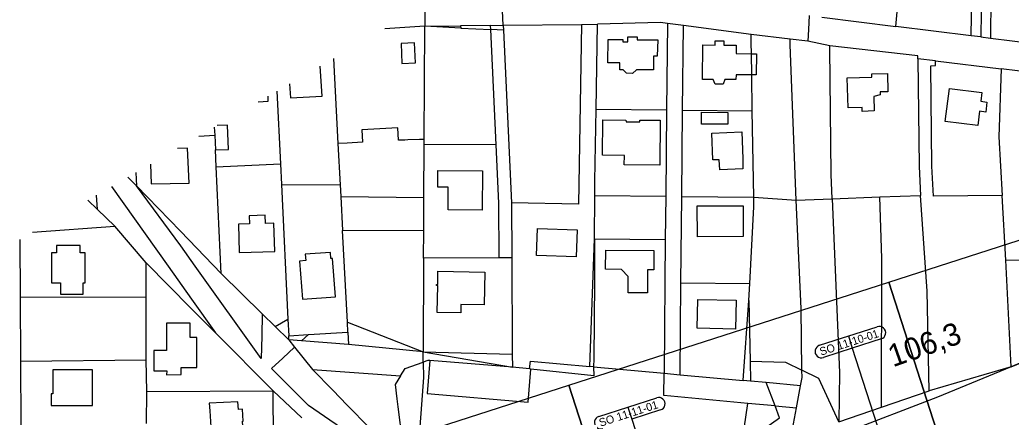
# Model space of a CAD drawing. Extents: x -758836 to -757729, y -1175316 to -1174366.
# Drawn here: x -758589.2 to -758279.4, y -1174765.3 to -1174641.1 of the extents above; entities that cross this region are included whole.
import ezdxf

# ---------------------------------------------------------------- set-up
doc = ezdxf.new("R2010")
doc.units = 0
for name, color, linetype in [('_NOR-návrh tenká', 7, 'Continuous'), ('_NOR-pomocná', 7, 'Continuous'), ('_NOR-popis', 7, 'Continuous'), ('G_Obvod stavby', 7, 'Continuous'), ('Hranice parcel', 7, 'Continuous'), ('Vrstva 7', 7, 'Continuous')]:
    doc.layers.add(name, color=color, linetype=linetype)

msp = doc.modelspace()

# ---------------------------------------------------------------- linework, layer by layer
at = {"layer": '_NOR-návrh tenká'}
msp.add_arc((-758205.34, -1175057.86), 295.6, 97.0978, 129.2849, dxfattribs=at)
at = {"layer": '_NOR-pomocná'}
for p, q in [((-758330.28, -1174739.89), (-758329.06, -1174743.7)), ((-758399.22, -1174762.1), (-758398, -1174765.9))]:
    msp.add_line(p, q, dxfattribs=at)
for points in [[(-758317.65, -1174723.03), (-758217.71, -1174690.84), (-758172.18, -1174832.19), (-758272.12, -1174864.38)], [(-758417.59, -1174755.22), (-758317.65, -1174723.03), (-758272.12, -1174864.38), (-758372.07, -1174896.57)], [(-758517.54, -1174787.42), (-758417.59, -1174755.22), (-758372.07, -1174896.57), (-758472.01, -1174928.76)]]:
    msp.add_lwpolyline(points, close=True, dxfattribs=at)
at = {"layer": '_NOR-popis'}
for points in [[(-758339.33, -1174742.8), (-758321.24, -1174736.98)], [(-758320.02, -1174740.79), (-758329.06, -1174743.7), (-758315.87, -1174784.63)], [(-758329.06, -1174743.7), (-758338.1, -1174746.61)], [(-758408.27, -1174765.01), (-758390.18, -1174759.18)], [(-758388.95, -1174762.99), (-758398, -1174765.9), (-758378.82, -1174825.45)]]:
    msp.add_lwpolyline(points, dxfattribs=at)
for centre, start, end in [((-758320.63, -1174738.88), 287.8533, 107.854), ((-758338.71, -1174744.71), 107.854, 287.8547), ((-758389.57, -1174761.09), 287.8533, 107.854), ((-758407.65, -1174766.91), 107.854, 287.8547)]:
    msp.add_arc(centre, 2, start, end, dxfattribs=at)
at = {"layer": 'G_Obvod stavby'}
msp.add_lwpolyline([(-758392.72, -1174840.76), (-758391.23, -1174838.56), (-758368.37, -1174821.64), (-758340.31, -1174807.33), (-758320.27, -1174796.89), (-758301, -1174790.21), (-758267.96, -1174782.93), (-758224.96, -1174775.27), (-758184.87, -1174772.83), (-758142.71, -1174770.26), (-758089.84, -1174768.68), (-758106.02, -1174731.44), (-758149.09, -1174725.67), (-758199.62, -1174726.6), (-758225.76, -1174732.36), (-758252.17, -1174738.18), (-758254.97, -1174739.34), (-758266.58, -1174744.16), (-758279.45, -1174749.49), (-758302.42, -1174759.02), (-758331.68, -1174770.24), (-758367.17, -1174799.81), (-758405.64, -1174832.2)], dxfattribs=at)
at = {"layer": 'Hranice parcel'}
for p, q in [((-758285.46, -1174607.47), (-758285.9, -1174646.82)), ((-758338.6, -1174640.24), (-758315.47, -1174643.12)), ((-758462.68, -1174643.09), (-758475.19, -1174643.89)), ((-758462.85, -1174678.46), (-758462.68, -1174643.09)), ((-758462.68, -1174643.09), (-758451.46, -1174642.95)), ((-758451.39, -1174643.67), (-758462.68, -1174643.09)), ((-758442.12, -1174642.84), (-758451.46, -1174642.95)), ((-758451.46, -1174642.95), (-758451.39, -1174643.67)), ((-758442.12, -1174642.84), (-758438.13, -1174642.79)), ((-758442.06, -1174644.14), (-758442.12, -1174642.84)), ((-758438.13, -1174642.79), (-758413.7, -1174642.5)), ((-758438.13, -1174642.79), (-758438.05, -1174644.35)), ((-758413.7, -1174642.5), (-758414.62, -1174698.66)), ((-758413.7, -1174642.5), (-758408.7, -1174642.44)), ((-758409.14, -1174669.01), (-758408.7, -1174642.44)), ((-758386.84, -1174642.22), (-758387.1, -1174669.22)), ((-758381.85, -1174642.89), (-758386.84, -1174642.22)), ((-758382.1, -1174669.27), (-758381.85, -1174642.89)), ((-758360.69, -1174645.71), (-758381.85, -1174642.89)), ((-758291.89, -1174646.05), (-758315.47, -1174643.12)), ((-758451.39, -1174643.67), (-758442.06, -1174644.14)), ((-758438.05, -1174644.35), (-758442.06, -1174644.14)), ((-758440.39, -1174680.2), (-758442.06, -1174644.14)), ((-758438.05, -1174644.35), (-758435.54, -1174698.32)), ((-758348.5, -1174647.1), (-758360.69, -1174645.71)), ((-758288.89, -1174646.43), (-758291.89, -1174646.05)), ((-758288.89, -1174646.43), (-758285.9, -1174646.82)), ((-758342.92, -1174647.74), (-758348.5, -1174647.1)), ((-758336.11, -1174649.25), (-758342.92, -1174647.74)), ((-758285.9, -1174646.82), (-758261.03, -1174649.91)), ((-758360.49, -1174658.29), (-758360.6, -1174651.67)), ((-758491.19, -1174653.13), (-758489.78, -1174679.76)), ((-758303.07, -1174653.93), (-758308.57, -1174653.26)), ((-758303.07, -1174653.93), (-758282.56, -1174656.41)), ((-758360.31, -1174669.48), (-758360.49, -1174658.29)), ((-758266.75, -1174658.35), (-758282.56, -1174656.41)), ((-758508.89, -1174663.35), (-758507.79, -1174686.07)), ((-758409.14, -1174669.01), (-758387.1, -1174669.22)), ((-758387.1, -1174669.22), (-758387.36, -1174696.22)), ((-758382.36, -1174696.27), (-758382.1, -1174669.27)), ((-758382.1, -1174669.27), (-758360.31, -1174669.48)), ((-758359.87, -1174696.48), (-758360.31, -1174669.48)), ((-758533.22, -1174677.4), (-758528.3, -1174677.14)), ((-758528.42, -1174674.62), (-758528.3, -1174677.14)), ((-758528.3, -1174677.14), (-758528.09, -1174681.75)), ((-758489.78, -1174679.76), (-758489.1, -1174692.62)), ((-758462.93, -1174696.59), (-758462.86, -1174680.09)), ((-758462.86, -1174680.09), (-758462.85, -1174678.46)), ((-758440.39, -1174680.2), (-758462.86, -1174680.09)), ((-758527.85, -1174687.07), (-758528.09, -1174681.75)), ((-758527.85, -1174687.07), (-758507.79, -1174686.07)), ((-758507.79, -1174686.07), (-758507.47, -1174692.57)), ((-758552.91, -1174688.76), (-758552.78, -1174692.96)), ((-758526.24, -1174720.38), (-758527.85, -1174687.07)), ((-758555.41, -1174690.21), (-758552.78, -1174692.96)), ((-758507.47, -1174692.57), (-758489.1, -1174692.62)), ((-758507.47, -1174692.57), (-758505.43, -1174734.65)), ((-758489.1, -1174692.62), (-758488.9, -1174696.33)), ((-758409.59, -1174709.5), (-758409.52, -1174696)), ((-758409.52, -1174696), (-758387.36, -1174696.22)), ((-758320.43, -1174696.43), (-758307.71, -1174695.96)), ((-758281.06, -1174716.22), (-758282.22, -1174695.95)), ((-758488.9, -1174696.33), (-758488.35, -1174706.88)), ((-758488.9, -1174696.33), (-758462.93, -1174696.59)), ((-758462.98, -1174706.79), (-758462.93, -1174696.59)), ((-758414.62, -1174698.66), (-758435.54, -1174698.32)), ((-758435.54, -1174698.32), (-758435.46, -1174715.46)), ((-758387.36, -1174696.22), (-758387.49, -1174709.72)), ((-758382.62, -1174723.27), (-758382.36, -1174696.27)), ((-758382.36, -1174696.27), (-758359.87, -1174696.48)), ((-758359.87, -1174696.48), (-758346.61, -1174697.42)), ((-758346.61, -1174697.42), (-758335.32, -1174696.99)), ((-758335.32, -1174696.99), (-758320.43, -1174696.43)), ((-758559.48, -1174705.52), (-758564.95, -1174700.34)), ((-758585.29, -1174707.46), (-758559.48, -1174705.52)), ((-758549.77, -1174716.98), (-758559.48, -1174705.52)), ((-758488.35, -1174706.88), (-758462.98, -1174706.79)), ((-758486.83, -1174735.54), (-758488.35, -1174706.88)), ((-758463.02, -1174715.59), (-758462.98, -1174706.79)), ((-758589.2, -1174709.72), (-758589.11, -1174727.75)), ((-758411.05, -1174749.38), (-758409.59, -1174709.5)), ((-758409.59, -1174709.5), (-758387.49, -1174709.72)), ((-758549.68, -1174727.61), (-758549.77, -1174716.98)), ((-758463.02, -1174715.59), (-758463.16, -1174744.79)), ((-758439.46, -1174715.47), (-758463.02, -1174715.59)), ((-758435.46, -1174715.46), (-758439.46, -1174715.47)), ((-758281.06, -1174716.22), (-758266.93, -1174716.05)), ((-758279.45, -1174749.49), (-758281.06, -1174716.22)), ((-758526.24, -1174720.38), (-758513.43, -1174732.97)), ((-758382.9, -1174751.98), (-758382.62, -1174723.27)), ((-758382.62, -1174723.27), (-758361.11, -1174723.47)), ((-758361.4, -1174728.81), (-758361.11, -1174723.47)), ((-758589.11, -1174727.75), (-758549.68, -1174727.61)), ((-758589.11, -1174727.75), (-758589.01, -1174747.74)), ((-758549.7, -1174747.29), (-758549.68, -1174727.61)), ((-758363.13, -1174753.8), (-758361.4, -1174728.81)), ((-758361.4, -1174728.81), (-758361.02, -1174747.72)), ((-758513.43, -1174732.97), (-758509.4, -1174736.93)), ((-758509.4, -1174736.93), (-758505.43, -1174734.65)), ((-758505.43, -1174734.65), (-758505.18, -1174739.86)), ((-758486.66, -1174738.69), (-758486.83, -1174735.54)), ((-758486.83, -1174735.54), (-758463.16, -1174744.79)), ((-758510.04, -1174757.06), (-758528.03, -1174738.91)), ((-758509.4, -1174736.93), (-758505.12, -1174741.14)), ((-758498.99, -1174739.47), (-758486.66, -1174738.69)), ((-758486.66, -1174738.69), (-758486.46, -1174742.55)), ((-758505.18, -1174739.86), (-758498.99, -1174739.47)), ((-758505.12, -1174741.14), (-758505.18, -1174739.86)), ((-758501.16, -1174741.44), (-758505.12, -1174741.14)), ((-758505.12, -1174741.14), (-758503.32, -1174743.41)), ((-758498.99, -1174739.47), (-758501.16, -1174741.44)), ((-758486.46, -1174742.55), (-758501.16, -1174741.44)), ((-758503.32, -1174743.41), (-758497.78, -1174750.4)), ((-758463.16, -1174744.79), (-758486.46, -1174742.55)), ((-758463.16, -1174744.79), (-758435.31, -1174745.59)), ((-758463.12, -1174748.03), (-758463.16, -1174744.79)), ((-758463.16, -1174744.79), (-758435.29, -1174749.65)), ((-758435.31, -1174745.59), (-758435.29, -1174749.65)), ((-758279.45, -1174749.49), (-758266.58, -1174744.16)), ((-758589.01, -1174747.74), (-758549.7, -1174747.29)), ((-758589.01, -1174747.74), (-758588.92, -1174767.73)), ((-758549.49, -1174757.19), (-758549.7, -1174747.29)), ((-758435.29, -1174749.65), (-758461.07, -1174747.52)), ((-758361.02, -1174747.72), (-758360.89, -1174754.01)), ((-758497.78, -1174750.4), (-758470.24, -1174752.31)), ((-758429.95, -1174750.16), (-758435.29, -1174749.65)), ((-758429.49, -1174750.29), (-758429.95, -1174750.16)), ((-758409.9, -1174749.48), (-758411.05, -1174749.38)), ((-758409.9, -1174749.48), (-758387.89, -1174751.51)), ((-758387.96, -1174758.53), (-758387.89, -1174751.51)), ((-758387.89, -1174751.51), (-758382.9, -1174751.98)), ((-758279.45, -1174749.49), (-758305.02, -1174756.99)), ((-758382.9, -1174751.98), (-758363.13, -1174753.8)), ((-758360.89, -1174754.01), (-758363.13, -1174753.8)), ((-758356.02, -1174754.46), (-758360.89, -1174754.01)), ((-758353.2, -1174761.75), (-758356.02, -1174754.46)), ((-758345.23, -1174755.46), (-758356.02, -1174754.46)), ((-758549.63, -1174767.27), (-758549.49, -1174757.19)), ((-758549.49, -1174757.19), (-758510.04, -1174757.06)), ((-758509.88, -1174777.17), (-758510.04, -1174757.06)), ((-758501.06, -1174765.48), (-758510.04, -1174757.06)), ((-758346.51, -1174762.37), (-758345.23, -1174755.46)), ((-758319.98, -1174762.15), (-758305.02, -1174756.99)), ((-758471.37, -1174759.51), (-758471.06, -1174761.99)), ((-758361.69, -1174760.96), (-758387.96, -1174758.53)), ((-758363.58, -1174773.76), (-758361.69, -1174760.96)), ((-758353.2, -1174761.75), (-758361.69, -1174760.96)), ((-758353.2, -1174761.75), (-758346.51, -1174762.37)), ((-758349.61, -1174779.02), (-758346.51, -1174762.37)), ((-758333.29, -1174766.74), (-758319.98, -1174762.15))]:
    msp.add_line(p, q, dxfattribs=at)
for points in [[(-758288.91, -1174575.86), (-758288.5, -1174594.53), (-758288.43, -1174615.42), (-758288.89, -1174646.43)], [(-758315.47, -1174643.12), (-758313.89, -1174626.1), (-758314.16, -1174610.46)], [(-758291.89, -1174646.05), (-758291.43, -1174615.38), (-758291.45, -1174610.38)], [(-758438.13, -1174642.79), (-758438.34, -1174638.23), (-758462.65, -1174637.48), (-758462.68, -1174643.09)], [(-758342.58, -1174639.74), (-758342.77, -1174644.13), (-758342.92, -1174647.74)], [(-758386.84, -1174642.22), (-758389.02, -1174641.93), (-758408.7, -1174642.44)], [(-758396.28, -1174646.41), (-758396.27, -1174647.3), (-758389.86, -1174647.38), (-758390, -1174652.41), (-758391.19, -1174652.41), (-758391.17, -1174656.75), (-758396.49, -1174656.68), (-758397.7, -1174657.89), (-758399.64, -1174657.78), (-758400.71, -1174656.69), (-758401.69, -1174656.68), (-758401.68, -1174654.49), (-758405.46, -1174654.5), (-758405.36, -1174647.21), (-758400.75, -1174647.27), (-758400.76, -1174647.97), (-758399.25, -1174647.98), (-758399.24, -1174646.39), (-758396.28, -1174646.41)], [(-758360.6, -1174651.67), (-758360.65, -1174648.31), (-758360.69, -1174645.71)], [(-758469.78, -1174654.76), (-758465.54, -1174654.56), (-758465.83, -1174648.3), (-758470.08, -1174648.5), (-758469.78, -1174654.76)], [(-758360.49, -1174658.29), (-758365.4, -1174658.26), (-758365.41, -1174659.77), (-758368.86, -1174659.75), (-758369.38, -1174661.24), (-758371.96, -1174661.21), (-758372.54, -1174659.73), (-758375.85, -1174659.7), (-758375.81, -1174648.94), (-758371.88, -1174648.98), (-758371.89, -1174647.69), (-758369.24, -1174647.7), (-758369.24, -1174649), (-758365.35, -1174649.03), (-758365.37, -1174651.63), (-758360.6, -1174651.67)], [(-758346.61, -1174697.42), (-758348.43, -1174648.94), (-758348.5, -1174647.1)], [(-758335.32, -1174696.99), (-758335.63, -1174689.39), (-758336.1, -1174649.9), (-758336.11, -1174649.25)], [(-758308.57, -1174653.26), (-758308.58, -1174652.32), (-758336.11, -1174649.25)], [(-758360.6, -1174651.67), (-758359.03, -1174651.68), (-758359.07, -1174658.3), (-758360.49, -1174658.29)], [(-758504.93, -1174661.06), (-758504.66, -1174665.51), (-758494.75, -1174664.89), (-758495.34, -1174655.52)], [(-758308.57, -1174653.26), (-758308.17, -1174686.94), (-758307.71, -1174695.96)], [(-758282.22, -1174695.95), (-758303.68, -1174696.21), (-758304.17, -1174686.81), (-758304.54, -1174655.43), (-758303.04, -1174655.41), (-758303.07, -1174653.93)], [(-758326, -1174668.45), (-758330.39, -1174668.59), (-758330.71, -1174659.18), (-758322.96, -1174658.96), (-758322.99, -1174657.98), (-758318.1, -1174657.83), (-758317.91, -1174663.57), (-758320.35, -1174663.62), (-758320.32, -1174664.52), (-758322.37, -1174665.07), (-758322.25, -1174669.56), (-758325.98, -1174669.75), (-758326, -1174668.45)], [(-758282.56, -1174656.41), (-758283.27, -1174677.6), (-758282.22, -1174695.95)], [(-758514.67, -1174666.68), (-758511.56, -1174666.52), (-758511.64, -1174664.94)], [(-758298.73, -1174662.53), (-758288.59, -1174663.75), (-758288.93, -1174666.52), (-758286.98, -1174666.77), (-758287.37, -1174669.93), (-758289.32, -1174669.66), (-758289.87, -1174674.12), (-758300.02, -1174672.9), (-758298.73, -1174662.53)], [(-758409.52, -1174696), (-758409.5, -1174691.51), (-758409.14, -1174669.01)], [(-758376.18, -1174673.69), (-758376.17, -1174669.97), (-758367.96, -1174670.04), (-758367.96, -1174673.74), (-758376.18, -1174673.69)], [(-758528.09, -1174681.75), (-758523.95, -1174681.56), (-758524.31, -1174673.96), (-758527.53, -1174674.11)], [(-758399.78, -1174672.4), (-758399.77, -1174672.92), (-758395.44, -1174672.93), (-758395.43, -1174672.45), (-758389.14, -1174672.47), (-758389.22, -1174686.54), (-758400.3, -1174686.45), (-758400.28, -1174683.45), (-758407.11, -1174683.39), (-758407.06, -1174672.37), (-758399.78, -1174672.4)], [(-758462.85, -1174678.46), (-758464.35, -1174678.51), (-758467.93, -1174678.64), (-758468.93, -1174678.66), (-758470.9, -1174678.72), (-758471.11, -1174674.89), (-758482.35, -1174675.5), (-758482.15, -1174679.34), (-758486.93, -1174679.6), (-758489.78, -1174679.76)], [(-758363.59, -1174676.12), (-758363.3, -1174684.53), (-758363.25, -1174687.66), (-758370.5, -1174687.93), (-758370.66, -1174684.8), (-758372.66, -1174684.86), (-758372.97, -1174676.48), (-758363.59, -1174676.12)], [(-758439.46, -1174715.47), (-758439.54, -1174698.42), (-758440.39, -1174680.2)], [(-758548.41, -1174686.16), (-758548.11, -1174692.38), (-758536.32, -1174692.16), (-758536.83, -1174681.21), (-758539.96, -1174681.29)], [(-758458.58, -1174693.4), (-758458.55, -1174688.18), (-758444.67, -1174688.27), (-758444.76, -1174700.56), (-758455.38, -1174700.51), (-758455.33, -1174693.42), (-758458.58, -1174693.4)], [(-758552.78, -1174692.96), (-758539.03, -1174707.17), (-758526.24, -1174720.38)], [(-758513.43, -1174732.97), (-758513.55, -1174739.95), (-758513.8, -1174746.93), (-758534.39, -1174718.05), (-758538.89, -1174711.74), (-758552.78, -1174692.96)], [(-758564.95, -1174700.34), (-758565.19, -1174695.86)], [(-758560.57, -1174693.18), (-758542.88, -1174718.04), (-758535.53, -1174728.37), (-758528.03, -1174738.91)], [(-758305.02, -1174756.99), (-758305.68, -1174725.91), (-758307.71, -1174695.96)], [(-758564.95, -1174700.34), (-758567.98, -1174697.47)], [(-758361.11, -1174723.47), (-758359.82, -1174699.56), (-758359.87, -1174696.48)], [(-758344.78, -1174750.56), (-758345.05, -1174731.32), (-758346.61, -1174697.42)], [(-758335.32, -1174696.99), (-758333.07, -1174751.31), (-758333.29, -1174766.74)], [(-758319.98, -1174762.15), (-758319.82, -1174715.66), (-758320.43, -1174696.43)], [(-758512.53, -1174702.11), (-758517.56, -1174702.34), (-758517.48, -1174704.89), (-758520.88, -1174704.99), (-758520.61, -1174713.81), (-758509.54, -1174713.47), (-758509.81, -1174704.65), (-758512.45, -1174704.73), (-758512.53, -1174702.11)], [(-758363.16, -1174699.19), (-758363.15, -1174708.8), (-758377.47, -1174708.85), (-758377.5, -1174699.23), (-758363.16, -1174699.19)], [(-758415.33, -1174715.11), (-758427.71, -1174714.73), (-758427.46, -1174706.34), (-758415.07, -1174706.71), (-758415.33, -1174715.11)], [(-758409.59, -1174709.5), (-758409.65, -1174723), (-758409.88, -1174746.98), (-758409.9, -1174749.48)], [(-758387.49, -1174709.72), (-758387.62, -1174723.22), (-758387.89, -1174751.51)], [(-758579.33, -1174723.26), (-758576.48, -1174723.28), (-758576.48, -1174726.78), (-758569.38, -1174726.78), (-758569.38, -1174723.28), (-758568.82, -1174723.27), (-758568.82, -1174713.94), (-758570.37, -1174713.94), (-758570.37, -1174711.62), (-758577.77, -1174711.65), (-758577.77, -1174713.95), (-758579.33, -1174713.95), (-758579.33, -1174723.26)], [(-758499.86, -1174716.33), (-758501.81, -1174716.48), (-758500.88, -1174728.4), (-758490.54, -1174727.6), (-758491.47, -1174715.66), (-758492.01, -1174715.7), (-758492.16, -1174713.75), (-758500.01, -1174714.36), (-758499.86, -1174716.33)], [(-758399.13, -1174726.37), (-758399.05, -1174721.25), (-758401.16, -1174719.15), (-758406.15, -1174719.02), (-758406.07, -1174713.02), (-758391.05, -1174713.22), (-758391.13, -1174719.22), (-758393.01, -1174719.21), (-758393.11, -1174726.43), (-758399.13, -1174726.37)], [(-758528.03, -1174738.91), (-758535.61, -1174731.27), (-758549.77, -1174716.98)], [(-758435.46, -1174715.46), (-758435.32, -1174744.65), (-758435.31, -1174745.59)], [(-758458.53, -1174719.65), (-758443.93, -1174719.93), (-758444.11, -1174730.17), (-758451.37, -1174730.05), (-758451.42, -1174732.69), (-758458.75, -1174732.55), (-758458.61, -1174724.15), (-758458.99, -1174724.14), (-758458.98, -1174723.76), (-758458.6, -1174723.77), (-758458.53, -1174719.65)], [(-758377.57, -1174737.45), (-758377.35, -1174728.49), (-758365.35, -1174728.74), (-758365.55, -1174737.75), (-758377.57, -1174737.45)], [(-758543.34, -1174751.98), (-758538.77, -1174751.93), (-758538.76, -1174749.76), (-758533.87, -1174749.74), (-758533.92, -1174740.33), (-758535.97, -1174740.34), (-758536.01, -1174735.85), (-758543.38, -1174735.9), (-758543.36, -1174744.4), (-758547.35, -1174744.41), (-758547.36, -1174750.79), (-758543.31, -1174750.78), (-758543.34, -1174751.98)], [(-758466.28, -1174780.52), (-758466.54, -1174782.53), (-758466.7, -1174783.79), (-758499, -1174761.63), (-758510.58, -1174750.09), (-758507.04, -1174746.79), (-758503.32, -1174743.41)], [(-758470.24, -1174752.31), (-758468.8, -1174750.02), (-758463.12, -1174748.03)], [(-758463.12, -1174748.03), (-758463.07, -1174752.81), (-758464.86, -1174776.68)], [(-758461.07, -1174747.52), (-758461.67, -1174747.53), (-758463.12, -1174748.03)], [(-758461.07, -1174747.52), (-758461.94, -1174757.82), (-758430.38, -1174760.57), (-758429.49, -1174750.29)], [(-758429.95, -1174750.16), (-758429.61, -1174747.73), (-758411.05, -1174749.38)], [(-758361.02, -1174747.72), (-758349.91, -1174748.04), (-758344.78, -1174750.56)], [(-758578.91, -1174757.94), (-758579.4, -1174757.94), (-758579.39, -1174761.63), (-758566.45, -1174761.62), (-758566.46, -1174750.43), (-758578.93, -1174750.46), (-758578.91, -1174757.94)], [(-758497.78, -1174750.4), (-758491.43, -1174756.87), (-758486.91, -1174761.48), (-758479.92, -1174768.61), (-758466.28, -1174780.52)], [(-758409.9, -1174749.48), (-758409.78, -1174752.31), (-758429.49, -1174750.29)], [(-758345.23, -1174755.46), (-758344.75, -1174752.89), (-758344.78, -1174750.56)], [(-758333.29, -1174766.74), (-758339.51, -1174753.16), (-758344.78, -1174750.56)], [(-758279.45, -1174749.49), (-758302.42, -1174759.02), (-758331.68, -1174770.24)], [(-758470.24, -1174752.31), (-758471.93, -1174755.02), (-758471.37, -1174759.51)], [(-758529.99, -1174760.86), (-758529.84, -1174763.25), (-758529.19, -1174773.23), (-758523.57, -1174772.91), (-758523.49, -1174774.21), (-758519.13, -1174774.01), (-758519.21, -1174772.67), (-758519.57, -1174766.55), (-758519.37, -1174766.54), (-758519.6, -1174762.74), (-758520.82, -1174762.81), (-758521.03, -1174760.42), (-758529.99, -1174760.86)], [(-758471.06, -1174761.99), (-758469.72, -1174772.68), (-758464.86, -1174776.68)], [(-758363.58, -1174773.76), (-758351.79, -1174765.46), (-758353.2, -1174761.75)]]:
    msp.add_lwpolyline(points, dxfattribs=at)

# ---------------------------------------------------------------- texts
at = {"layer": '_NOR-popis'}
for s, p in [('SO 11-10-01', (-758338.8, -1174746.05)), ('SO 11-11-01', (-758407.74, -1174768.26))]:
    msp.add_text(s, height=2.5, rotation=17.854, dxfattribs=at).set_placement(p)
at = {"layer": 'Vrstva 7'}
msp.add_text('106,3', height=6.972, rotation=19.4575, dxfattribs=at).set_placement((-758316.36, -1174749.69))

doc.saveas('drawing.dxf')
